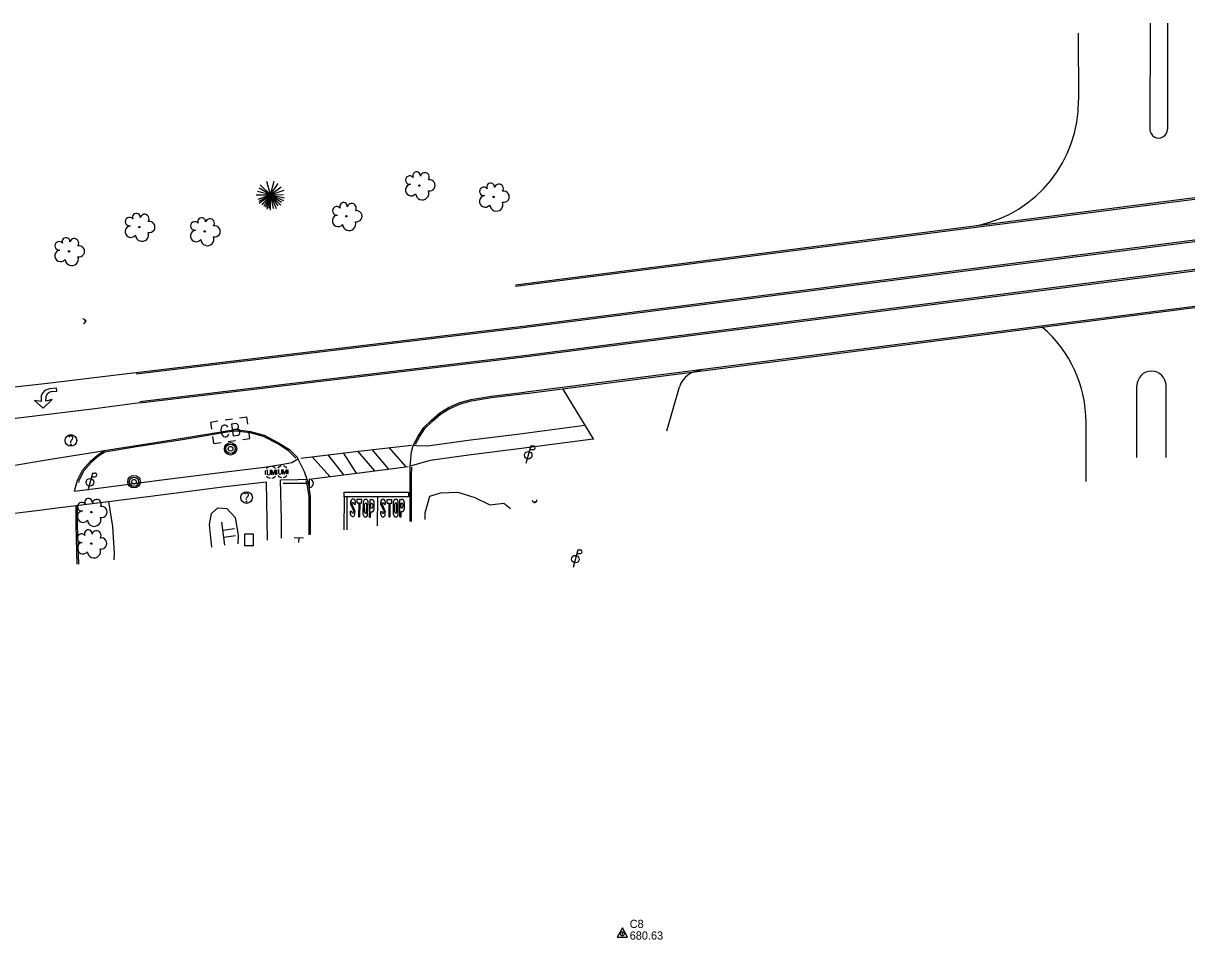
# Model space of a CAD drawing. Extents: x 2129547 to 2134906, y 657330 to 659734.
# Drawn here: x 2132931.6 to 2133330, y 657497.1 to 657811 of the extents above; entities that cross this region are included whole.
import ezdxf

# ---------------------------------------------------------------- set-up
doc = ezdxf.new("R2010")
doc.units = 0
for name, color, linetype in [('Default', 7, 'Continuous'), ('DR_X_Cells', 7, 'Continuous'), ('PM_X_Arrows', 7, 'Continuous'), ('PM_X_Cells', 7, 'Continuous'), ('PM_X_CL', 7, 'Continuous'), ('PM_X_Crosswalk', 7, 'Continuous'), ('PM_X_Stop_Line2', 7, 'Continuous'), ('PM_X_Transverse_Line', 7, 'Continuous'), ('PV_X_Curb', 7, 'Continuous'), ('PV_X_CURB2', 7, 'Continuous'), ('PV_X_EOP', 7, 'Continuous'), ('PV_X_EOP2', 7, 'Continuous'), ('PV_X_Parking_Lot', 7, 'Continuous'), ('PV_X_Walk', 7, 'Continuous'), ('PV_X_WALK2', 7, 'Continuous'), ('RD_X_Concrete_Pad', 7, 'Continuous'), ('RD_X_Misc_Items', 7, 'Continuous'), ('SG_X_Detection', 7, 'Continuous'), ('SN_X_Public', 7, 'Continuous'), ('SV_P_Aerial_Targets', 7, 'Continuous'), ('UT_X_Electric_Cells', 7, 'Continuous'), ('UT_X_Misc_Cells', 7, 'Continuous'), ('UT_X_Unknown_Cells', 7, 'Continuous'), ('VG_X_Cells', 7, 'Continuous'), ('VG_X_Flower_Bed', 7, 'Continuous'), ('VG_X_Tree_Line_Lt', 7, 'Continuous'), ('X-STM-TXT', 7, 'Continuous')]:
    doc.layers.add(name, color=color, linetype=linetype)

# ---------------------------------------------------------------- blocks, each defined once
blk = doc.blocks.new('DM')
at = {"layer": 'UT_X_Misc_Cells'}
blk.add_circle((0, 0), 0.00254, dxfattribs=at)
blk.add_arc((0.01016, 0), 0.01016, 90, 270, dxfattribs=at)
blk = doc.blocks.new('FCTRL')
at = {"layer": 'SV_P_Aerial_Targets'}
blk.add_lwpolyline([(-0.0229, -0.0147), (0.0229, -0.0147), (0, 0.0262)], close=True, dxfattribs=at)
for radius in [0.00889, 0.00203]:
    blk.add_circle((0, 0), radius, dxfattribs=at)
blk = doc.blocks.new('PP')
at = {"layer": 'UT_X_Electric_Cells'}
for p, q in [((0.0109, 0.0406), (-0.0095, -0.0356)), ((0.0065, 0.0244), (0.0217, 0.0244)), ((0.0109, 0.0406), (0.0217, 0.0406))]:
    blk.add_line(p, q, dxfattribs=at)
blk.add_circle((0, 0), 0.0165, dxfattribs=at)
blk.add_arc((0.0218, 0.0325), 0.0081, 268.8767, 91.1233, dxfattribs=at)
blk = doc.blocks.new('SGN1P')
at = {"layer": 'SN_X_Public'}
for p, q in [((0, 0), (-0.02032, 0)), ((0, 0.02032), (0, -0.02032))]:
    blk.add_line(p, q, dxfattribs=at)
blk = doc.blocks.new('POINT_DISPLAY')
at = {"layer": 'Default'}
blk.add_line((0, 0), (0, 0), dxfattribs=at)
blk = doc.blocks.new('SGN2P')
at = {"layer": 'Default'}
for p, q in [((0, 0.0203), (0, -0.0203)), ((0, 0.0061), (-0.0203, 0.0061)), ((0, -0.0061), (-0.0203, -0.0061))]:
    blk.add_line(p, q, dxfattribs=at)
blk.add_blockref('POINT_DISPLAY', (0, 0), dxfattribs=at)
blk = doc.blocks.new('TREE')
at = {"layer": 'VG_X_Cells'}
blk.add_circle((0, 0), 0.00305, dxfattribs=at)
for centre, radius, start, end in [((-0.0125, 0.0428), 0.0167, 354.0047, 205.9741), ((0.0232, 0.0359), 0.0197, 323.83, 165.0376), ((-0.0362, -0.0197), 0.0251, 96.1722, 320.5737), ((-0.042, 0.0237), 0.0187, 39.0625, 279.5412), ((0.0439, 0.0005), 0.0243, 259.1453, 101.4596), ((0.012, -0.0331), 0.029, 184.9476, 19.4572)]:
    blk.add_arc(centre, radius, start, end, dxfattribs=at)
blk = doc.blocks.new('UMH')
at = {"layer": 'UT_X_Unknown_Cells'}
for p, q in [((-0.017, 0.0104), (-0.017, -0.0059)), ((-0.0042, 0.0104), (-0.0042, -0.0059))]:
    blk.add_line(p, q, dxfattribs=at)
blk.add_lwpolyline([(0.0024, -0.01), (0.0024, 0.0104), (0.0099, -0.01), (0.0174, 0.0104), (0.0174, -0.01)], dxfattribs=at)
for centre, radius, start, end in [((0, 0), 0.0254, 160.0169, 200.0392), ((0, 0), 0.0254, 100.0806, 140.0721), ((0, 0), 0.0254, 40.0577, 80.1061), ((0, 0), 0.0254, 340.0169, 20.0392), ((0, 0), 0.0254, 220.0577, 260.0473), ((-0.0106, -0.0029), 0.00708, 205.1924, 334.8076), ((0, 0), 0.0254, 280.0114, 320.0264)]:
    blk.add_arc(centre, radius, start, end, dxfattribs=at)
blk = doc.blocks.new('UOBJ')
at = {"layer": 'RD_X_Misc_Items'}
blk.add_line((0, -0.0096), (0, -0.0036), dxfattribs=at)
for centre, radius in [((0, 0), 0.0254), ((0, -0.0179), 0.00216)]:
    blk.add_circle(centre, radius, dxfattribs=at)
for centre, radius, start, end in [((-0.0008, 0.0103), 0.00957, 88.324, 152.5385), ((-0.0002, 0.0111), 0.00873, 291.9329, 92.4584), ((0.0074, -0.003), 0.00746, 125.4618, 184.0829)]:
    blk.add_arc(centre, radius, start, end, dxfattribs=at)
blk = doc.blocks.new('ETREE')
at = {"layer": 'VG_X_Cells'}
for p, q in [((0, 0), (-0.0157, 0.0586)), ((0, 0), (0.016, 0.0597)), ((-0.0627, 0), (0, 0)), ((0, 0), (-0.056, 0.015)), ((0, 0), (-0.0545, -0.0198)), ((0, 0), (-0.0506, -0.029)), ((0, 0), (-0.0496, 0.0292)), ((0, 0), (-0.0496, -0.038)), ((0, 0), (-0.0443, 0.0443)), ((0, 0), (-0.0374, -0.044)), ((0, 0), (-0.0294, -0.051)), ((0, 0), (-0.0211, -0.0551)), ((0, 0), (-0.016, -0.0617)), ((0, 0), (-0.0069, -0.0583)), ((0, 0), (0.0337, 0.0493)), ((0, 0), (0.0464, 0.0356)), ((0, 0), (0.0602, 0.0204)), ((0, 0), (0.0573, 0.0012)), ((0, -0.0665), (0, 0)), ((0, 0), (0.0117, -0.0589)), ((0, 0), (0.0246, -0.0593)), ((0, 0), (0.0322, -0.0482)), ((0, 0), (0.0456, -0.0447)), ((0, 0), (0.0485, -0.0324)), ((0, 0), (0.0567, -0.0247)), ((0, 0), (0.0613, -0.0122))]:
    blk.add_line(p, q, dxfattribs=at)
blk = doc.blocks.new('GCB-X')
at = {"layer": 'Default'}
for p, q in [((-0.0317, 0.019), (-0.019, 0.019)), ((-0.0317, 0.0063), (-0.0317, 0.019)), ((-0.0063, 0.019), (0.0063, 0.019)), ((0.0034, 0.0007), (0.0124, 0.0007)), ((0.019, 0.019), (0.0317, 0.019)), ((0.0317, 0.0063), (0.0317, 0.019)), ((-0.0317, -0.019), (-0.0317, -0.0063)), ((-0.0317, -0.019), (-0.019, -0.019)), ((-0.0063, -0.019), (0.0063, -0.019)), ((0.019, -0.019), (0.0317, -0.019)), ((0.0317, -0.019), (0.0317, -0.0063))]:
    blk.add_line(p, q, dxfattribs=at)
blk.add_lwpolyline([(0.0116, 0.0099), (0.0034, 0.0099), (0.0034, -0.0104), (0.0124, -0.0104)], dxfattribs=at)
for centre, radius, start, end in [((0.0071, 0), 0.0233, 164.8107, 195.1893), ((-0.0094, 0.0037), 0.00645, 21.5603, 158.4397), ((0.0101, 0.0051), 0.00501, 296.8207, 73.0013), ((0.0101, -0.0049), 0.00597, 292.0547, 67.9453), ((-0.0094, -0.0037), 0.00645, 201.5603, 338.4397)]:
    blk.add_arc(centre, radius, start, end, dxfattribs=at)
for p in [(0, 0.019), (0, 0.019), (-0.0317, 0), (0, 0), (0, 0), (0, 0), (0, -0.019), (0, -0.019), (0.0317, 0)]:
    blk.add_blockref('POINT_DISPLAY', p, dxfattribs=at)
blk = doc.blocks.new('PMLFT')
at = {"layer": 'PM_X_Cells'}
for points in [[(-0.57, 0), (-0.57, 0), (-0.57, 0.17), (0, 0), (-0.65, 0.76), (-1.54, 0.08), (-0.98, 0.17), (-0.98, -0.01)], [(-1.56, -0.59), (-2.03, -0.59), (-2.03, -0.85), (-1.4, -0.85)]]:
    blk.add_lwpolyline(points, dxfattribs=at)
for centre, radius, end in [((-1.56, -0.01), 0.583, 0), ((-1.4, -0.01), 0.833, 0.9085)]:
    blk.add_arc(centre, radius, 270, end, dxfattribs=at)
blk = doc.blocks.new('PEDPB')
at = {"layer": 'Default'}
blk.add_line((0.0457, 0), (0, 0), dxfattribs=at)
blk.add_lwpolyline([(0.0457, -0.0071), (0.0457, -0.0071), (0.0457, 0.0071), (0.0457, 0.0071)], dxfattribs=at)
blk.add_arc((0.0457, 0), 0.00711, 270.0002, 89.9998, dxfattribs=at)
blk = doc.blocks.new('PMST6')
at = {"layer": 'PM_X_Cells'}
for p, q in [((-1.33, 1.02), (-1.06, 1.02)), ((-0.47, 1.02), (-1.07, 0.73)), ((-1.06, 1.02), (-1.06, 0.92)), ((-0.47, 1.02), (-0.19, 1.02)), ((-0.19, 1.02), (-0.46, 1.02)), ((-0.32, 0.32), (-1.52, 0.32)), ((-1.52, 0.32), (-1.52, 0.23)), ((-0.32, 0.23), (-1.52, 0.23)), ((-1.33, 0.64), (-1.05, 0.64)), ((-1.11, 0.92), (-1.06, 0.92)), ((-1.11, 0.73), (-1.07, 0.73)), ((-0.45, 0.92), (-1.05, 0.64)), ((-0.41, 0.73), (-0.46, 0.73)), ((-0.46, 0.64), (-0.46, 0.73)), ((-0.19, 0.64), (-0.46, 0.64)), ((-0.45, 0.92), (-0.41, 0.92)), ((-0.32, 0.47), (-0.32, 0.32)), ((-0.32, 0.47), (0, 0.47)), ((-0.32, 0.23), (-0.32, 0.08)), ((-0.32, 0.08), (0, 0.08)), ((0, 0.47), (0, 0.08)), ((-1.52, -0.64), (0, -0.64)), ((-1.52, -0.64), (-1.52, -0.73)), ((-1.52, -0.73), (-1.06, -0.73)), ((-1.33, -0.08), (-0.19, -0.08)), ((-1.33, -0.47), (-0.19, -0.47)), ((-1.11, -0.18), (-0.41, -0.18)), ((-1.11, -0.37), (-0.41, -0.37)), ((-1.06, -0.73), (-1.06, -0.76)), ((-0.75, -0.73), (-0.75, -0.77)), ((-0.75, -0.73), (-0.32, -0.73)), ((-0.6, -0.92), (-0.47, -0.92)), ((-0.32, -0.73), (-0.32, -0.77)), ((0, -0.64), (0, -0.76)), ((-0.81, -1.02), (-0.25, -1.02))]:
    blk.add_line(p, q, dxfattribs=at)
for centre, radius, start, end in [((-1.33, 0.83), 0.191, 90, 270), ((-0.19, 0.83), 0.191, 270, 90), ((-1.11, 0.83), 0.0953, 90, 270.0001), ((-0.41, 0.83), 0.0953, 270, 90.0001), ((-1.33, -0.28), 0.191, 90, 269.997), ((-1.11, -0.28), 0.0953, 90, 269.997), ((-0.81, -0.76), 0.254, 180, 270), ((-0.6, -0.77), 0.148, 180, 270), ((-0.47, -0.77), 0.148, 270, 0), ((-0.41, -0.28), 0.0953, 270.003, 90), ((-0.25, -0.76), 0.254, 270, 0), ((-0.19, -0.28), 0.191, 270.003, 90)]:
    blk.add_arc(centre, radius, start, end, dxfattribs=at)
blk = doc.blocks.new('MH1D-X')
at = {"layer": 'Defpoints'}
blk.add_circle((0, 0), 0.508, dxfattribs=at)
blk.add_circle((0, 0), 0.508, dxfattribs=at)
at = {"layer": 'DR_X_Cells'}
for radius in [0.677, 0.254]:
    blk.add_circle((0, 0), radius, dxfattribs=at)

msp = doc.modelspace()

# ---------------------------------------------------------------- linework, layer by layer
at = {"layer": 'PM_X_CL'}
for p, q in [((2132970.25, 657691.37), (2133101.8, 657707.16)), ((2132970.31, 657690.87), (2133101.86, 657706.67)), ((2132971.52, 657681.47), (2133103.07, 657697.25)), ((2132971.58, 657680.97), (2133103.14, 657696.75))]:
    msp.add_line(p, q, dxfattribs=at)
for points in [[(2132771.32, 657656.52), (2132787.81, 657661.98), (2132804.1, 657668.65), (2132817.98, 657672.99), (2132831.31, 657675.72), (2132851.37, 657677.79), (2132873.64, 657680.39), (2132893.78, 657683.12), (2132917.28, 657685.24), (2132939.92, 657687.67), (2132969.08, 657691.25), (2132970.25, 657691.37)], [(2132971.58, 657680.97), (2132956.09, 657678.97), (2132931.86, 657676), (2132909.7, 657673.34), (2132885.36, 657670.4)]]:
    msp.add_lwpolyline(points, dxfattribs=at)
at = {"layer": 'PM_X_Crosswalk'}
for points in [[(2133026.62, 657662.07), (2133044.51, 657664.18), (2133064.55, 657666.53)], [(2133029.54, 657654.83), (2133046.72, 657657), (2133063.43, 657659.13)]]:
    msp.add_lwpolyline(points, dxfattribs=at)
at = {"layer": 'PM_X_Stop_Line2'}
for p, q in [((2133041.53, 657637.47), (2133041.56, 657648.74)), ((2133042.53, 657637.46), (2133042.56, 657648.73)), ((2133052.95, 657638.88), (2133053.02, 657648.64))]:
    msp.add_line(p, q, dxfattribs=at)
msp.add_lwpolyline([(2133063.57, 657648.77), (2133041.5, 657648.81), (2133041.51, 657650.41), (2133063.57, 657650.38)], close=True, dxfattribs=at)
at = {"layer": 'PM_X_Transverse_Line'}
for p, q in [((2133051.97, 657657.67), (2133046.23, 657664.39)), ((2133056.84, 657658.29), (2133051.04, 657664.95)), ((2133062.76, 657659.04), (2133056.93, 657665.64)), ((2133036.55, 657655.72), (2133030.52, 657662.53)), ((2133041.4, 657656.34), (2133035.98, 657663.17)), ((2133045.67, 657656.87), (2133041.32, 657663.81))]:
    msp.add_line(p, q, dxfattribs=at)
at = {"layer": 'PV_X_Curb'}
for points in [[(2133064.61, 657640.39), (2133064.57, 657656.01), (2133064.64, 657658.94)], [(2133028.37, 657654.42), (2133028.63, 657653.69), (2133029.35, 657648.87), (2133029.41, 657637.99), (2133029.39, 657635.83)], [(2132950.61, 657625.75), (2132950.24, 657639.14), (2132950.2, 657645.5)]]:
    msp.add_lwpolyline(points, dxfattribs=at)
at = {"layer": 'PV_X_CURB2'}
for p, q in [((2133100.14, 657721.41), (2133759.21, 657806.01)), ((2133104.73, 657684.35), (2133763.81, 657768.95))]:
    msp.add_line(p, q, dxfattribs=at)
for points in [[(2133065.92, 657666.88), (2133067.28, 657669.32), (2133069.16, 657672.2), (2133071.7, 657674.71), (2133074.51, 657677.16), (2133077.51, 657678.93), (2133081.29, 657680.63), (2133085.15, 657681.68), (2133091.93, 657682.81), (2133102.44, 657684.07), (2133104.73, 657684.35)], [(2133024.93, 657662.07), (2133022.41, 657664.56), (2133018.77, 657666.9), (2133013.88, 657669.43), (2133009.29, 657670.7), (2133004.48, 657671.31), (2133001.4, 657670.93), (2132986.18, 657668.37), (2132970.34, 657665.92), (2132959.54, 657664.15), (2132957.36, 657662.69), (2132955, 657660.66), (2132952.33, 657657.7), (2132950.7, 657654.36), (2132950.5, 657653.65)]]:
    msp.add_lwpolyline(points, dxfattribs=at)
at = {"layer": 'PV_X_EOP'}
for p, q in [((2133317.47, 657810.99), (2133317.38, 657774.69)), ((2133323.47, 657810.97), (2133323.38, 657774.68)), ((2133292.78, 657807.55), (2133292.96, 657784.67)), ((2133101.8, 657707.16), (2133760.87, 657791.76)), ((2133101.86, 657706.67), (2133760.94, 657791.27)), ((2133103.07, 657697.25), (2133762.15, 657781.84)), ((2133103.14, 657696.75), (2133762.21, 657781.35)), ((2133116.34, 657685.68), (2133126.86, 657668.39)), ((2133152, 657671.42), (2133156.35, 657686.52)), ((2133312.94, 657662.31), (2133312.94, 657686.86)), ((2133322.94, 657662.31), (2133322.94, 657686.86)), ((2133295.53, 657654.08), (2133295.53, 657674.29))]:
    msp.add_line(p, q, dxfattribs=at)
for centre, radius, start, end in [((2133249.41, 657784.33), 43.55, 282.0405, 0.4422), ((2133320.38, 657774.68), 3, 179.8626, 359.8626), ((2133252.46, 657674.29), 43.07, 0, 49.2831), ((2133163.43, 657684.48), 7.37, 86.7591, 163.921), ((2133317.94, 657686.86), 5, 0, 180)]:
    msp.add_arc(centre, radius, start, end, dxfattribs=at)
at = {"layer": 'PV_X_EOP2'}
for p, q in [((2133100.2, 657720.92), (2133759.27, 657805.51)), ((2133104.66, 657684.85), (2133763.74, 657769.45))]:
    msp.add_line(p, q, dxfattribs=at)
for points in [[(2133064.11, 657640.33), (2133064.07, 657656.02), (2133064.15, 657659.27), (2133064.18, 657660.35), (2133064.58, 657664.21), (2133065.12, 657666.32), (2133065.2, 657666.61), (2133066.85, 657669.58), (2133068.77, 657672.52), (2133071.36, 657675.07), (2133074.22, 657677.57), (2133077.28, 657679.38), (2133081.12, 657681.11), (2133085.04, 657682.17), (2133091.86, 657683.31), (2133102.38, 657684.57), (2133104.66, 657684.85)], [(2132925.36, 657659.07), (2132941.64, 657661.81), (2132955.96, 657664.07), (2132959.35, 657664.63), (2132970.26, 657666.41), (2132986.1, 657668.87), (2133001.33, 657671.43), (2133004.48, 657671.81), (2133009.39, 657671.19), (2133014.06, 657669.9), (2133019.02, 657667.34), (2133022.73, 657664.95), (2133025.37, 657662.34), (2133025.63, 657661.82), (2133027.85, 657657.49), (2133028.75, 657654.87), (2133029.12, 657653.81), (2133029.85, 657648.91), (2133029.91, 657637.99), (2133029.89, 657635.89)], [(2132949.15, 657650.77), (2132950.23, 657654.54), (2132951.91, 657657.98), (2132954.65, 657661.02), (2132957.05, 657663.09), (2132959.35, 657664.63)]]:
    msp.add_lwpolyline(points, dxfattribs=at)
at = {"layer": 'PV_X_Parking_Lot'}
msp.add_lwpolyline([(2132950.11, 657625.69), (2132949.74, 657639.13), (2132949.7, 657645.8)], dxfattribs=at)
at = {"layer": 'PV_X_Walk'}
msp.add_lwpolyline([(2133020.08, 657634.62), (2133020, 657640.78), (2133019.7, 657654.6), (2133025.64, 657654.76), (2133028.75, 657654.87)], dxfattribs=at)
at = {"layer": 'PV_X_WALK2'}
for points in [[(2133123.96, 657673.22), (2133101.61, 657670.31), (2133084, 657668.04), (2133069.98, 657666.15), (2133066.28, 657666.29), (2133065.12, 657666.32)], [(2133126.75, 657668.57), (2133102.24, 657665.4), (2133084.99, 657663.14), (2133070.96, 657661.23), (2133064.15, 657659.27)], [(2132949.15, 657650.77), (2132959.13, 657652.01), (2132979.06, 657654.64), (2133000.12, 657657.29), (2133014.25, 657658.93), (2133020.57, 657659.97), (2133023.61, 657660.55), (2133025.63, 657661.82)], [(2132921.87, 657642.37), (2132937.12, 657644.25), (2132943.07, 657644.98), (2132949.7, 657645.8), (2132959.76, 657647.05), (2132960.79, 657647.19), (2132979.68, 657649.65), (2133000.77, 657652.32), (2133014.78, 657653.96), (2133015, 657640.71), (2133015.09, 657633.97)]]:
    msp.add_lwpolyline(points, dxfattribs=at)
at = {"layer": 'RD_X_Concrete_Pad'}
msp.add_lwpolyline([(2133007.49, 657631.99), (2133007.54, 657636.13), (2133010.35, 657636.09), (2133010.3, 657632.01)], close=True, dxfattribs=at)
at = {"layer": 'VG_X_Flower_Bed'}
for points in [[(2132960.79, 657647.19), (2132962.15, 657638.66), (2132962.69, 657629.34), (2132962.6, 657627.26)], [(2132995.8, 657634.76), (2132995.33, 657639.29), (2132996.05, 657643.13), (2132998.28, 657645.02), (2133001.37, 657644.84), (2133004.17, 657641.74), (2133005.24, 657635.7), (2133005.07, 657632.67)], [(2132996.2, 657631.52), (2132996.15, 657631.66), (2132995.8, 657634.76)]]:
    msp.add_lwpolyline(points, dxfattribs=at)
at = {"layer": 'VG_X_Tree_Line_Lt'}
msp.add_lwpolyline([(2133069.26, 657640.99), (2133069.22, 657643.33), (2133070.87, 657648.98), (2133074.48, 657650.21), (2133080.41, 657650.34), (2133086.23, 657648.58), (2133091.35, 657646.04), (2133096.12, 657646.58), (2133098.42, 657644.77)], dxfattribs=at)

# ---------------------------------------------------------------- block references
at = {"layer": 'DR_X_Cells', "xscale": 196.85000000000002, "yscale": 196.85000000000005, "rotation": 8.20749050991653}
msp.add_blockref('GCB-X', (2133002.52, 657671.61), dxfattribs=at)
at = {"layer": 'PM_X_Arrows', "xscale": 3.9370000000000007, "yscale": 3.9370000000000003, "rotation": -173.38845168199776}
msp.add_blockref('PMLFT', (2132935.49, 657681.8), dxfattribs=at)
at = {"layer": 'PM_X_Stop_Line2'}
for p, xscale, yscale, rotation in [((2133047.84, 657647.93), 3.9370000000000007, 3.9370000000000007, 88.15905083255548), ((2133058.09, 657647.93), 3.937, 3.9370000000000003, 89.98593076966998)]:
    msp.add_blockref('PMST6', p, dxfattribs=dict(at, xscale=xscale, yscale=yscale, rotation=rotation))
at = {"layer": 'RD_X_Misc_Items', "xscale": 78.74000000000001, "yscale": 78.74000000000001}
for p in [(2132947.93, 657668.1), (2133008.08, 657648.56)]:
    msp.add_blockref('UOBJ', p, dxfattribs=at)
at = {"layer": 'SG_X_Detection', "xscale": 196.85000000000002, "yscale": 196.85000000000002}
msp.add_blockref('PEDPB', (2133020.61, 657653.41), dxfattribs=at)
at = {"layer": 'SN_X_Public'}
for name, p, xscale, yscale, rotation in [('SGN2P', (2133000.16, 657636.18), 196.85000000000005, 196.85000000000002, -172.3282883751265), ('SGN1P', (2133025.94, 657634.77), 78.74000000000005, 78.74000000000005, 88.50560816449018)]:
    msp.add_blockref(name, p, dxfattribs=dict(at, xscale=xscale, yscale=yscale, rotation=rotation))
at = {"layer": 'SV_P_Aerial_Targets', "xscale": 78.74000000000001, "yscale": 78.74000000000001}
msp.add_blockref('FCTRL', (2133136.75, 657499.14), dxfattribs=at)
at = {"layer": 'UT_X_Electric_Cells', "xscale": 78.74000000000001, "yscale": 78.74000000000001}
for p in [(2133104.51, 657663.05), (2132954.46, 657653.76), (2133120.67, 657627.45)]:
    msp.add_blockref('PP', p, dxfattribs=at)
at = {"layer": 'UT_X_Misc_Cells'}
for p, xscale, yscale, rotation in [((2132952.91, 657709.09), 78.74000000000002, 78.74000000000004, -168.70900501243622), ((2133106.81, 657646.92), 78.74, 78.74000000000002, 97.6874285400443)]:
    msp.add_blockref('DM', p, dxfattribs=dict(at, xscale=xscale, yscale=yscale, rotation=rotation))
at = {"layer": 'UT_X_Unknown_Cells', "xscale": 78.74000000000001, "yscale": 78.74000000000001}
for p in [(2133016.45, 657657.17), (2133020.33, 657657.38)]:
    msp.add_blockref('UMH', p, dxfattribs=at)
at = {"layer": 'VG_X_Cells', "xscale": 78.74000000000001, "yscale": 78.74000000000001}
for name, p in [('TREE', (2133067.28, 657755.41)), ('ETREE', (2133016.27, 657752.21)), ('TREE', (2133092.66, 657751.53)), ('TREE', (2133042.26, 657744.88)), ('TREE', (2132971.33, 657741.19)), ('TREE', (2132993.7, 657739.7)), ('TREE', (2132947.25, 657732.87)), ('TREE', (2132954.95, 657643.56)), ('TREE', (2132954.87, 657632.78))]:
    msp.add_blockref(name, p, dxfattribs=at)
at = {"layer": 'X-STM-TXT', "xscale": 3.1496000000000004, "yscale": 3.149600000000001}
for p in [(2133002.6, 657665.25), (2132969.53, 657653.97)]:
    msp.add_blockref('MH1D-X', p, dxfattribs=at)

# ---------------------------------------------------------------- texts
at = {"layer": 'SV_P_Aerial_Targets'}
for s, p in [('C8', (2133139.27, 657501.14)), ('680.63', (2133139.27, 657497.15))]:
    msp.add_text(s, height=2.8, dxfattribs=at).set_placement(p)

doc.saveas('drawing.dxf')
